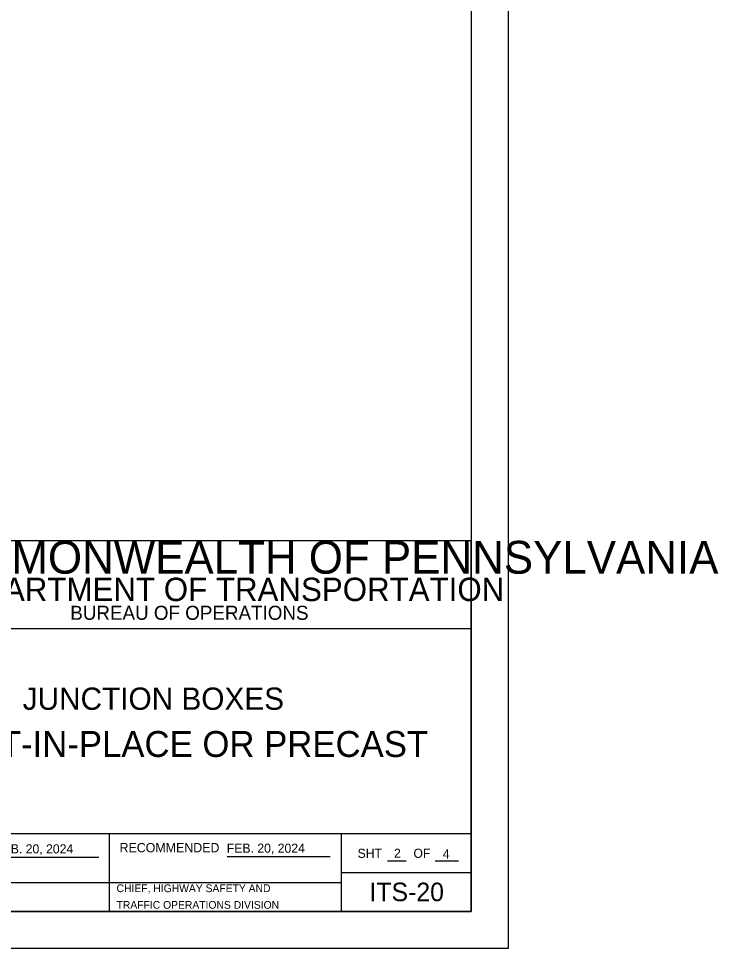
# Model space of a CAD drawing. Extents: x 1299104.8 to 1299141.6, y 239639.8 to 239661.8.
# Drawn here: x 1299132.2 to 1299141.64, y 239639.8 to 239652.34 of the extents above; entities that cross this region are included whole.
import ezdxf

# ---------------------------------------------------------------- set-up
doc = ezdxf.new("R2010")
doc.units = 0
for name, color, linetype in [('1', 7, 'Continuous'), ('2', 7, 'Continuous'), ('DIM TXT', 7, 'Continuous'), ('GS_noplot_1', 7, 'Continuous'), ('GS_plotshape_p', 7, 'Continuous'), ('Level 1', 7, 'Continuous'), ('PTEXT', 7, 'Continuous')]:
    doc.layers.add(name, color=color, linetype=linetype)

msp = doc.modelspace()

# ---------------------------------------------------------------- linework, layer by layer
at = {"layer": '1'}
for p, q in [((1299131.894, 239641.03), (1299133.284, 239641.03)), ((1299135.016, 239641.039), (1299136.405, 239641.039)), ((1299137.176, 239640.983), (1299137.427, 239640.983)), ((1299137.819, 239640.983), (1299138.133, 239640.983)), ((1299130.302, 239640.69), (1299133.427, 239640.69))]:
    msp.add_line(p, q, dxfattribs=at)
at = {"layer": 'GS_noplot_1'}
msp.add_lwpolyline([(1299130.302, 239641.349), (1299136.552, 239641.349), (1299136.552, 239640.301), (1299130.302, 239640.301)], close=True, dxfattribs=at)
at = {"layer": 'GS_plotshape_p'}
msp.add_lwpolyline([(1299104.802, 239661.801), (1299138.802, 239661.801), (1299138.802, 239639.801), (1299104.802, 239639.801)], close=True, dxfattribs=at)
at = {"layer": 'Level 1'}
for p, q in [((1299130.302, 239641.349), (1299138.302, 239641.349)), ((1299133.427, 239641.349), (1299133.427, 239640.301)), ((1299136.552, 239640.825), (1299138.302, 239640.825)), ((1299133.427, 239640.69), (1299136.552, 239640.69))]:
    msp.add_line(p, q, dxfattribs=at)
for points in [[(1299138.302, 239640.301), (1299106.302, 239640.301), (1299106.302, 239661.301), (1299138.302, 239661.301)], [(1299138.302, 239645.294), (1299130.302, 239645.294), (1299130.302, 239644.114), (1299138.302, 239644.114)], [(1299138.302, 239645.294), (1299130.302, 239645.294), (1299130.302, 239640.301), (1299138.302, 239640.301)]]:
    msp.add_lwpolyline(points, close=True, dxfattribs=at)

# ---------------------------------------------------------------- texts
at = {"layer": '1'}
for s, height, p in [('COMMONWEALTH OF PENNSYLVANIA', 0.44223, (1299130.728, 239644.853)), ('DEPARTMENT OF TRANSPORTATION', 0.31514, (1299131.141, 239644.484)), ('BUREAU OF OPERATIONS', 0.18955, (1299132.901, 239644.231)), ('FEB. 20, 2024', 0.12303, (1299131.889, 239641.082)), ('RECOMMENDED', 0.125, (1299133.565, 239641.097)), ('FEB. 20, 2024', 0.12303, (1299135.011, 239641.091)), ('CHIEF, HIGHWAY SAFETY AND ', 0.10417, (1299133.525, 239640.56)), ('TRAFFIC OPERATIONS DIVISION', 0.10417, (1299133.525, 239640.336))]:
    msp.add_text(s, height=height, dxfattribs=at).set_placement(p)
at = {"layer": '2'}
for s, p in [('SHT', (1299136.773, 239641.022)), ('2', (1299137.264, 239641.023)), ('OF', (1299137.526, 239641.022)), ('4', (1299137.921, 239641.013))]:
    msp.add_text(s, height=0.123, dxfattribs=at).set_placement(p)
at = {"layer": 'DIM TXT'}
msp.add_text('ITS-20', height=0.25, dxfattribs=at).set_placement((1299136.934, 239640.438))
at = {"layer": 'PTEXT'}
for s, height, p in [('JUNCTION BOXES', 0.3, (1299132.26, 239643.018)), ('CAST-IN-PLACE OR PRECAST', 0.35, (1299130.989, 239642.382))]:
    msp.add_text(s, height=height, dxfattribs=at).set_placement(p)

doc.saveas('drawing.dxf')
